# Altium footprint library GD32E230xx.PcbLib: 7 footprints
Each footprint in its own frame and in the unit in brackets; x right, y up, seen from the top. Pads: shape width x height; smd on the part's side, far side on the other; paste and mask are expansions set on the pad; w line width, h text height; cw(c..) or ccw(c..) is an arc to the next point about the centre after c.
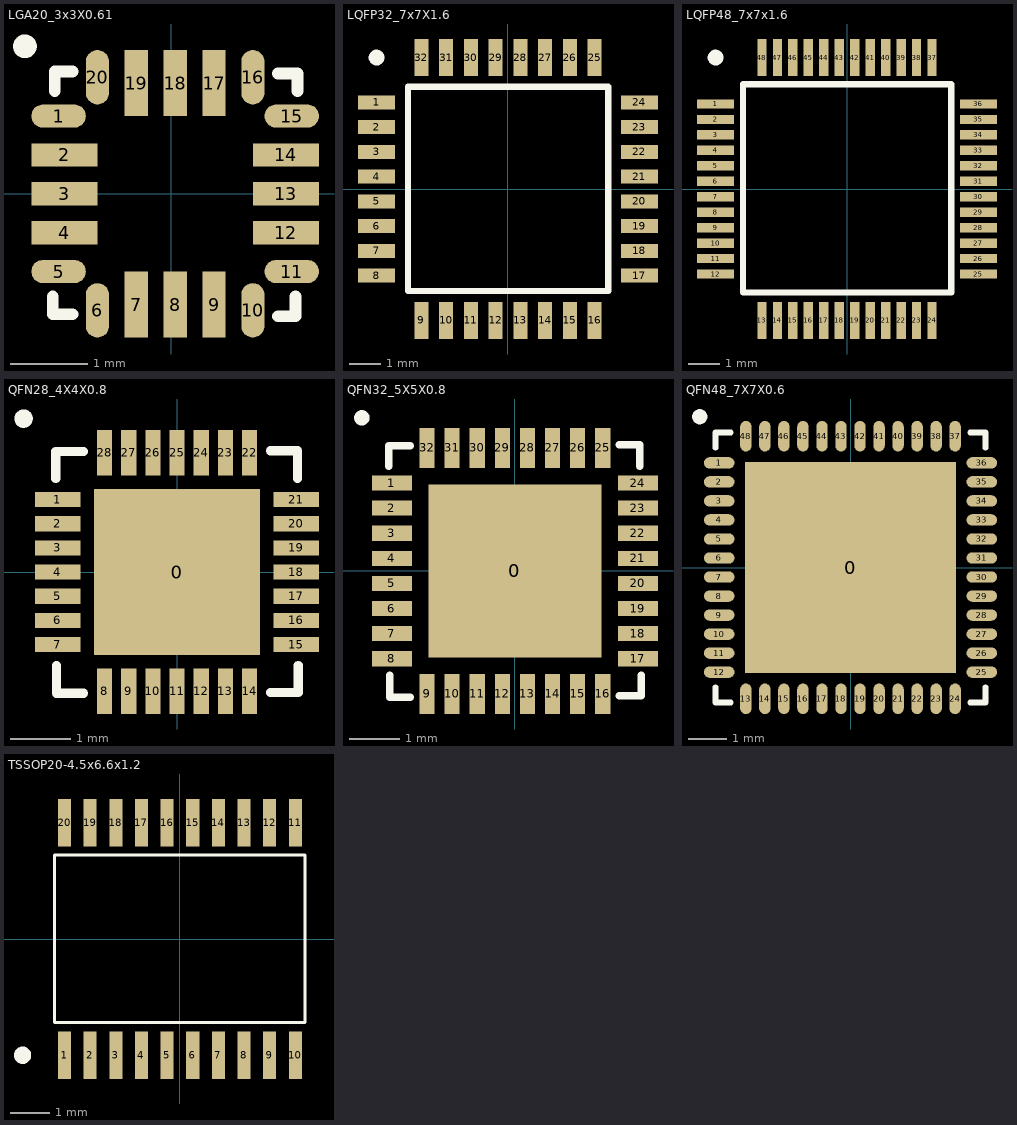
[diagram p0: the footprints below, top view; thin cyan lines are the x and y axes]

## LGA20_3x3X0.61 [mm]
pads (20):
  oval 0.7x0.3 smd mask+0.102: 1(-1.45,1)
  rect 0.85x0.3 smd: 2(-1.375,0.5) 3(-1.375,0) 4(-1.375,-0.5) 12(1.475,-0.5) 13(1.475,0) 14(1.475,0.5)
  oval 0.7x0.3 smd: 5(-1.45,-1) 11(1.55,-1) 15(1.55,1)
  oval 0.3x0.7 smd: 6(-0.95,-1.5) 10(1.05,-1.5) 16(1.05,1.5) 20(-0.95,1.5)
  rect 0.3x0.85 smd: 7(-0.45,-1.425) 8(0.05,-1.425) 9(0.55,-1.425) 17(0.55,1.425) 18(0.05,1.425) 19(-0.45,1.425)
Top Overlay:
  circle w0.152: c-1.883,1.897 r0.076
  lines w0.152: -1.526,-1.321 -1.526,-1.549 -1.272,-1.549 ; -1.499,1.321 -1.499,1.575 -1.27,1.575 ; 1.371,-1.576 1.599,-1.576 1.599,-1.322 ; 1.372,1.549 1.626,1.549 1.626,1.321

## LQFP32_7x7X1.6 [mm]
pads (32):
  rect 1.2x0.45 smd: 1(-4.25,2.8) 2(-4.25,2) 3(-4.25,1.2) 4(-4.25,0.4) 5(-4.25,-0.4) 6(-4.25,-1.2) 7(-4.25,-2) 8(-4.25,-2.8) 17(4.25,-2.8) 18(4.25,-2) 19(4.25,-1.2) 20(4.25,-0.4) 21(4.25,0.4) 22(4.25,1.2) 23(4.25,2) 24(4.25,2.8)
  rect 0.45x1.2 smd: 9(-2.8,-4.25) 10(-2,-4.25) 11(-1.2,-4.25) 12(-0.4,-4.25) 13(0.4,-4.25) 14(1.2,-4.25) 15(2,-4.25) 16(2.8,-4.25) 25(2.8,4.25) 26(2,4.25) 27(1.2,4.25) 28(0.4,4.25) 29(-0.4,4.25) 30(-1.2,4.25) 31(-2,4.25) 32(-2.8,4.25)
Top Overlay:
  circle w0.254: c-4.25,4.25 r0.127
  lines w0.203: -3.234,-3.296 -3.234,3.308 3.243,3.308 3.243,-3.296 -3.234,-3.296
3D body "TQFP80P900X900X160-32N.step": height 1.6, standoff 0, extent -4.5,-4.5 4.5,4.5

## LQFP48_7x7x1.6 [mm]
pads (48):
  rect 1.2x0.3 smd: 1(-4.25,2.75) 2(-4.25,2.25) 3(-4.25,1.75) 4(-4.25,1.25) 5(-4.25,0.75) 6(-4.25,0.25) 7(-4.25,-0.25) 8(-4.25,-0.75) 9(-4.25,-1.25) 10(-4.25,-1.75) 11(-4.25,-2.25) 12(-4.25,-2.75) 25(4.25,-2.75) 26(4.25,-2.25) 27(4.25,-1.75) 28(4.25,-1.25) 29(4.25,-0.75) 30(4.25,-0.25) 31(4.25,0.25) 32(4.25,0.75) 33(4.25,1.25) 34(4.25,1.75) 35(4.25,2.25) 36(4.25,2.75)
  rect 0.3x1.2 smd: 13(-2.75,-4.25) 14(-2.25,-4.25) 15(-1.75,-4.25) 16(-1.25,-4.25) 17(-0.75,-4.25) 18(-0.25,-4.25) 19(0.25,-4.25) 20(0.75,-4.25) 21(1.25,-4.25) 22(1.75,-4.25) 23(2.25,-4.25) 24(2.75,-4.25) 37(2.75,4.25) 38(2.25,4.25) 39(1.75,4.25) 40(1.25,4.25) 41(0.75,4.25) 42(0.25,4.25) 43(-0.25,4.25) 44(-0.75,4.25) 45(-1.25,4.25) 46(-1.75,4.25) 47(-2.25,4.25) 48(-2.75,4.25)
Top Overlay:
  circle w0.254: c-4.25,4.25 r0.127
  lines w0.203: -3.361,-3.346 -3.361,3.385 3.37,3.385 3.37,-3.346 -3.361,-3.346
3D body "TSQFP50P900X900X160-48N.step": height 1.6, standoff 0, extent -4.5,-4.5 4.5,4.5

## QFN28_4X4X0.8 [mm]
pads (29):
  rect 2.75x2.75 smd: 0(0,0)
  rect 0.75x0.25 smd: 1(-1.975,1.2) 2(-1.975,0.8) 3(-1.975,0.4) 4(-1.975,0) 5(-1.975,-0.4) 6(-1.975,-0.8) 7(-1.975,-1.2) 15(1.975,-1.2) 16(1.975,-0.8) 17(1.975,-0.4) 18(1.975,0) 19(1.975,0.4) 20(1.975,0.8) 21(1.975,1.2)
  rect 0.25x0.75 smd: 8(-1.2,-1.975) 9(-0.8,-1.975) 10(-0.4,-1.975) 11(0,-1.975) 12(0.4,-1.975) 13(0.8,-1.975) 14(1.2,-1.975) 22(1.2,1.975) 23(0.8,1.975) 24(0.4,1.975) 25(0,1.975) 26(-0.4,1.975) 27(-0.8,1.975) 28(-1.2,1.975)
Top Overlay:
  circle w0.152: c-2.54,2.54 r0.076
  lines w0.152: -2.007,1.549 -2.007,1.993 -1.549,1.993 ; -1.993,-1.549 -1.993,-2.007 -1.549,-2.007 ; 1.549,-1.993 2.007,-1.993 2.007,-1.549 ; 1.549,2.007 1.993,2.007 1.993,1.549
3D body "QFN40P400X400X80_HS-29N.step": height 0.8, standoff 0, extent -2.051,-2.051 2.051,2.051

## QFN32_5X5X0.8 [mm]
pads (33):
  rect 3.45x3.45 smd: 0(0,0)
  rect 0.8x0.3 smd: 1(-2.45,1.75) 2(-2.45,1.25) 3(-2.45,0.75) 4(-2.45,0.25) 5(-2.45,-0.25) 6(-2.45,-0.75) 7(-2.45,-1.25) 8(-2.45,-1.75) 17(2.45,-1.75) 18(2.45,-1.25) 19(2.45,-0.75) 20(2.45,-0.25) 21(2.45,0.25) 22(2.45,0.75) 23(2.45,1.25) 24(2.45,1.75)
  rect 0.3x0.8 smd: 9(-1.75,-2.45) 10(-1.25,-2.45) 11(-0.75,-2.45) 12(-0.25,-2.45) 13(0.25,-2.45) 14(0.75,-2.45) 15(1.25,-2.45) 16(1.75,-2.45) 25(1.75,2.45) 26(1.25,2.45) 27(0.75,2.45) 28(0.25,2.45) 29(-0.25,2.45) 30(-0.75,2.45) 31(-1.25,2.45) 32(-1.75,2.45)
Top Overlay:
  circle w0.152: c-3.048,3.048 r0.076
  lines w0.152: -2.515,2.083 -2.515,2.489 -2.083,2.489 ; -2.489,-2.083 -2.489,-2.515 -2.083,-2.515 ; 2.083,-2.489 2.515,-2.489 2.515,-2.083 ; 2.083,2.515 2.489,2.515 2.489,2.083
3D body "QFN50P500X500X80_HS-33N.step": height 0.8, standoff 0, extent -2.551,-2.551 2.551,2.551

## QFN48_7X7X0.6 [mm]
pads (49):
  rect 5.55x5.55 smd: 0(0,0)
  oval 0.8x0.3 smd: 1(-3.45,2.75) 2(-3.45,2.25) 3(-3.45,1.75) 4(-3.45,1.25) 5(-3.45,0.75) 6(-3.45,0.25) 7(-3.45,-0.25) 8(-3.45,-0.75) 9(-3.45,-1.25) 10(-3.45,-1.75) 11(-3.45,-2.25) 12(-3.45,-2.75) 25(3.45,-2.75) 26(3.45,-2.25) 27(3.45,-1.75) 28(3.45,-1.25) 29(3.45,-0.75) 30(3.45,-0.25) 31(3.45,0.25) 32(3.45,0.75) 33(3.45,1.25) 34(3.45,1.75) 35(3.45,2.25) 36(3.45,2.75)
  oval 0.3x0.8 smd: 13(-2.75,-3.45) 14(-2.25,-3.45) 15(-1.75,-3.45) 16(-1.25,-3.45) 17(-0.75,-3.45) 18(-0.25,-3.45) 19(0.25,-3.45) 20(0.75,-3.45) 21(1.25,-3.45) 22(1.75,-3.45) 23(2.25,-3.45) 24(2.75,-3.45) 37(2.75,3.45) 38(2.25,3.45) 39(1.75,3.45) 40(1.25,3.45) 41(0.75,3.45) 42(0.25,3.45) 43(-0.25,3.45) 44(-0.75,3.45) 45(-1.25,3.45) 46(-1.75,3.45) 47(-2.25,3.45) 48(-2.75,3.45)
Top Overlay:
  circle w0.254: c-3.962,3.962 r0.072
  lines w0.152: -3.551,-3.15 -3.551,-3.551 -3.15,-3.551 ; -3.551,3.15 -3.551,3.551 -3.15,3.551 ; 3.15,-3.551 3.551,-3.551 3.551,-3.15 ; 3.15,3.551 3.551,3.551 3.551,3.15
3D body "QFN50P700X700X60_HS-49N.step": height 0.6, standoff 0, extent -3.576,-3.551 3.526,3.551

## TSSOP20-4.5x6.6x1.2 [mm]
pads (20):
  rect 0.33x1.2 smd: 1(-2.925,-2.95) 2(-2.275,-2.95) 3(-1.625,-2.95) 4(-0.975,-2.95) 5(-0.325,-2.95) 6(0.325,-2.95) 7(0.975,-2.95) 8(1.625,-2.95) 9(2.275,-2.95) 10(2.925,-2.95) 11(2.925,2.95) 12(2.275,2.95) 13(1.625,2.95) 14(0.975,2.95) 15(0.325,2.95) 16(-0.325,2.95) 17(-0.975,2.95) 18(-1.625,2.95) 19(-2.275,2.95) 20(-2.925,2.95)
Top Overlay:
  circle w0.254: c-3.988,-2.946 r0.092
  lines w0.076: -3.179,-2.112 -3.179,2.13 3.171,2.13 3.171,-2.112 -3.179,-2.112
3D body "TSOP65P640X120-20N.step": height 1.2, standoff 0, extent -3.3,-3.2 3.3,3.2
